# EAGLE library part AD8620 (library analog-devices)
Precision, Very Low Noise, Low Input Bias Current, Wide Bandwidth JFET Operational Amplifiers Source: http://www.analog.com/static/imported-files/data_sheets/AD8610_8620.pdf
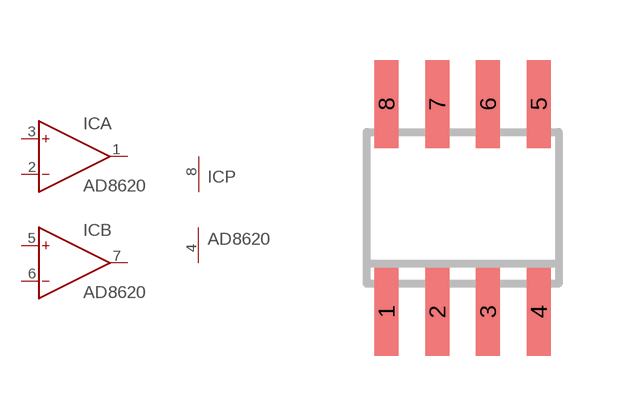
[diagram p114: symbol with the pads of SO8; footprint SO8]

Designator prefix IC; gates A=OP B=OP P=PWR+-

## AD8620R (MF: ALTERA CORPORATION; MPN: AD8620ARZ; OC_FARNELL: 9994386; OC_NEWARK: 59K6972)  [SO8]
1  A:OUT  out
2  A:IN-  in
3  A:IN+  in
4  P:V-  pwr
5  B:IN+  in
6  B:IN-  in
7  B:OUT  out
8  P:V+  pwr

## Footprint SO8 (pad centres in mm)
8-Lead Small Outline IC (SO-8) Source: http://www.analog.com/UploadedFiles/Data_Sheets/703465986AD8611_2_0.pdf
smd 0.6 x 2.2: 1 -1.905,-2.6; 2 -0.635,-2.6; 3 0.635,-2.6; 4 1.905,-2.6; 5 1.905,2.6; 6 0.635,2.6; 7 -0.635,2.6; 8 -1.905,2.6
